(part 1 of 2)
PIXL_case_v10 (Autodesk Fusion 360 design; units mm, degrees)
part number: 0.96Oled_W_4_Buttons
base_feature "Base Feature"
work_plane "WorkPlane1" AlongDistance -6.5 ExtraOffset 0
sketch "Sketch1" plane through (0, 0, -6.5) normal (0, 0, 1) x axis (1, 0, 0)
  line L1 (24.2, -27.5) -> (-24.2, -27.5)
  line L2 (24.2, 15.7) -> (24.2, -27.5)
  line L3 (-24.2, 15.7) -> (24.2, 15.7)
  line L4 (-24.2, -27.5) -> (-24.2, 15.7)
extrude "Extrude1" new body sketch "Sketch1" along normal blind 11.8
fillet "Fillet1" radius 5
fillet "Fillet2" radius 1.4
work_plane "WorkPlane2" AlongDistance -6.5 ExtraOffset 0
sketch "Sketch2" plane through (0, 0, -6.5) normal (0, 0, 1) x axis (1, 0, 0)
  line L1 (22.2, -25.5) -> (-22.2, -25.5)
  line L2 (22.2, 13.7) -> (22.2, -25.5)
  line L3 (-22.2, 13.7) -> (22.2, 13.7)
  line L4 (-22.2, -25.5) -> (-22.2, 13.7)
extrude "Extrude2" cut sketch "Sketch2" along normal blind 9.3
fillet "Fillet3" radius 1.7
work_plane "WorkPlane3" AlongDistance 2.79 ExtraOffset 0
sketch "Sketch3" plane through (0, 0, 2.79) normal (0, 0, 1) x axis (1, 0, 0)
  line L1 (20.7, -11.3) -> (11, -11.3)
  line L2 (20.7, 11.7) -> (20.7, -11.3)
  line L3 (11, 11.7) -> (20.7, 11.7)
  line L4 (11, -11.3) -> (11, 11.7)
extrude "Extrude3" cut sketch "Sketch3" along normal blind 1.56
work_plane "WorkPlane4" AlongDistance 2.79 ExtraOffset 0
sketch "Sketch4" plane through (0, 0, 2.79) normal (0, 0, 1) x axis (1, 0, 0)
  line L1 (10, 9.6) -> (-10.8, 9.6)
  line L2 (10, 12.2) -> (10, 9.6)
  line L3 (-10.8, 12.2) -> (10, 12.2)
  line L4 (-10.8, 9.6) -> (-10.8, 12.2)
extrude "Extrude4" cut sketch "Sketch4" along normal blind 0.91
work_plane "WorkPlane5" AlongDistance 4.34 ExtraOffset 0
sketch "Sketch5" plane through (0, 0, 4.34) normal (0, 0, 1) x axis (1, 0, 0)
  line L1 (12.1, 5.6) -> (11.5, 5.6)
  line L2 (12.1, 11.8) -> (12.1, 5.6)
  line L3 (11.5, 11.8) -> (12.1, 11.8)
  line L4 (11.5, 5.6) -> (11.5, 11.8)
extrude "Extrude5" cut sketch "Sketch5" along normal blind 1.06
work_plane "WorkPlane6" AlongDistance 4.34 ExtraOffset 0
sketch "Sketch6" plane through (0, 0, 4.34) normal (0, 0, 1) x axis (1, 0, 0)
  line L1 (19.6, 11.2) -> (11.5, 11.2)
  line L2 (19.6, 11.8) -> (19.6, 11.2)
  line L3 (11.5, 11.8) -> (19.6, 11.8)
  line L4 (11.5, 11.2) -> (11.5, 11.8)
extrude "Extrude6" cut sketch "Sketch6" along normal blind 1.06
work_plane "WorkPlane7" AlongDistance 4.34 ExtraOffset 0
sketch "Sketch7" plane through (0, 0, 4.34) normal (0, 0, 1) x axis (1, 0, 0)
  line L1 (19.6, 5.6) -> (11.5, 5.6)
  line L2 (19.6, 6.2) -> (19.6, 5.6)
  line L3 (11.5, 6.2) -> (19.6, 6.2)
  line L4 (11.5, 5.6) -> (11.5, 6.2)
extrude "Extrude7" cut sketch "Sketch7" along normal blind 1.06
work_plane "WorkPlane8" AlongDistance 4.34 ExtraOffset 0
sketch "Sketch8" plane through (0, 0, 4.34) normal (0, 0, 1) x axis (1, 0, 0)
  line L1 (12.1, -0.07) -> (11.5, -0.07)
  line L2 (12.1, 6.13) -> (12.1, -0.07)
  line L3 (11.5, 6.13) -> (12.1, 6.13)
  line L4 (11.5, -0.07) -> (11.5, 6.13)
extrude "Extrude8" cut sketch "Sketch8" along normal blind 1.06
work_plane "WorkPlane9" AlongDistance 4.34 ExtraOffset 0
sketch "Sketch9" plane through (0, 0, 4.34) normal (0, 0, 1) x axis (1, 0, 0)
  line L1 (19.6, 5.53) -> (11.5, 5.53)
  line L2 (19.6, 6.13) -> (19.6, 5.53)
  line L3 (11.5, 6.13) -> (19.6, 6.13)
  line L4 (11.5, 5.53) -> (11.5, 6.13)
extrude "Extrude9" cut sketch "Sketch9" along normal blind 1.06
work_plane "WorkPlane10" AlongDistance 4.34 ExtraOffset 0
sketch "Sketch10" plane through (0, 0, 4.34) normal (0, 0, 1) x axis (1, 0, 0)
  line L1 (19.6, -0.07) -> (11.5, -0.07)
  line L2 (19.6, 0.53) -> (19.6, -0.07)
  line L3 (11.5, 0.53) -> (19.6, 0.53)
  line L4 (11.5, -0.07) -> (11.5, 0.53)
extrude "Extrude10" cut sketch "Sketch10" along normal blind 1.06
work_plane "WorkPlane11" AlongDistance 4.34 ExtraOffset 0
sketch "Sketch11" plane through (0, 0, 4.34) normal (0, 0, 1) x axis (1, 0, 0)
  line L1 (12.1, -5.73) -> (11.5, -5.73)
  line L2 (12.1, 0.47) -> (12.1, -5.73)
  line L3 (11.5, 0.47) -> (12.1, 0.47)
  line L4 (11.5, -5.73) -> (11.5, 0.47)
extrude "Extrude11" cut sketch "Sketch11" along normal blind 1.06
work_plane "WorkPlane12" AlongDistance 4.34 ExtraOffset 0
sketch "Sketch12" plane through (0, 0, 4.34) normal (0, 0, 1) x axis (1, 0, 0)
  line L1 (19.6, -0.13) -> (11.5, -0.13)
  line L2 (19.6, 0.47) -> (19.6, -0.13)
  line L3 (11.5, 0.47) -> (19.6, 0.47)
  line L4 (11.5, -0.13) -> (11.5, 0.47)
extrude "Extrude12" cut sketch "Sketch12" along normal blind 1.06
work_plane "WorkPlane13" AlongDistance 4.34 ExtraOffset 0
sketch "Sketch13" plane through (0, 0, 4.34) normal (0, 0, 1) x axis (1, 0, 0)
  line L1 (19.6, -5.73) -> (11.5, -5.73)
  line L2 (19.6, -5.13) -> (19.6, -5.73)
  line L3 (11.5, -5.13) -> (19.6, -5.13)
  line L4 (11.5, -5.73) -> (11.5, -5.13)
extrude "Extrude13" cut sketch "Sketch13" along normal blind 1.06
work_plane "WorkPlane14" AlongDistance 4.34 ExtraOffset 0
sketch "Sketch14" plane through (0, 0, 4.34) normal (0, 0, 1) x axis (1, 0, 0)
  line L1 (12.1, -11.4) -> (11.5, -11.4)
  line L2 (12.1, -5.2) -> (12.1, -11.4)
  line L3 (11.5, -5.2) -> (12.1, -5.2)
  line L4 (11.5, -11.4) -> (11.5, -5.2)
extrude "Extrude14" cut sketch "Sketch14" along normal blind 1.06
work_plane "WorkPlane15" AlongDistance 4.34 ExtraOffset 0
sketch "Sketch15" plane through (0, 0, 4.34) normal (0, 0, 1) x axis (1, 0, 0)
  line L1 (19.6, -5.8) -> (11.5, -5.8)
  line L2 (19.6, -5.2) -> (19.6, -5.8)
  line L3 (11.5, -5.2) -> (19.6, -5.2)
  line L4 (11.5, -5.8) -> (11.5, -5.2)
extrude "Extrude15" cut sketch "Sketch15" along normal blind 1.06
work_plane "WorkPlane16" AlongDistance 4.34 ExtraOffset 0
sketch "Sketch16" plane through (0, 0, 4.34) normal (0, 0, 1) x axis (1, 0, 0)
  line L1 (19.6, -11.4) -> (11.5, -11.4)
  line L2 (19.6, -10.8) -> (19.6, -11.4)
  line L3 (11.5, -10.8) -> (19.6, -10.8)
  line L4 (11.5, -11.4) -> (11.5, -10.8)
extrude "Extrude16" cut sketch "Sketch16" along normal blind 1.06
work_plane "WorkPlane17" AlongDistance 4.34 ExtraOffset 0
sketch "Sketch17" plane through (0, 0, 4.34) normal (0, 0, 1) x axis (1, 0, 0)
  line L1 (20.7, 6.2) -> (18.4, 6.2)
  line L2 (20.7, 11.2) -> (20.7, 6.2)
  line L3 (18.4, 11.2) -> (20.7, 11.2)
  line L4 (18.4, 6.2) -> (18.4, 11.2)
extrude "Extrude17" cut sketch "Sketch17" along normal blind 0.46
work_plane "WorkPlane18" AlongDistance 4.34 ExtraOffset 0
sketch "Sketch18" plane through (0, 0, 4.34) normal (0, 0, 1) x axis (1, 0, 0)
  line L1 (20.7, 0.53) -> (18.4, 0.53)
  line L2 (20.7, 5.53) -> (20.7, 0.53)
  line L3 (18.4, 5.53) -> (20.7, 5.53)
  line L4 (18.4, 0.53) -> (18.4, 5.53)
extrude "Extrude18" cut sketch "Sketch18" along normal blind 0.46
work_plane "WorkPlane19" AlongDistance 4.34 ExtraOffset 0
sketch "Sketch19" plane through (0, 0, 4.34) normal (0, 0, 1) x axis (1, 0, 0)
  line L1 (20.7, -5.13) -> (18.4, -5.13)
  line L2 (20.7, -0.13) -> (20.7, -5.13)
  line L3 (18.4, -0.13) -> (20.7, -0.13)
  line L4 (18.4, -5.13) -> (18.4, -0.13)
extrude "Extrude19" cut sketch "Sketch19" along normal blind 0.46
work_plane "WorkPlane20" AlongDistance 4.34 ExtraOffset 0
sketch "Sketch20" plane through (0, 0, 4.34) normal (0, 0, 1) x axis (1, 0, 0)
  line L1 (20.7, -10.8) -> (18.4, -10.8)
  line L2 (20.7, -5.8) -> (20.7, -10.8)
  line L3 (18.4, -5.8) -> (20.7, -5.8)
  line L4 (18.4, -10.8) -> (18.4, -5.8)
extrude "Extrude20" cut sketch "Sketch20" along normal blind 0.46
work_plane "WorkPlane21" AlongDistance 2.79 ExtraOffset 0
sketch "Sketch21" plane through (0, 0, 2.79) normal (0, 0, 1) x axis (1, 0, 0)
  line L1 (7, -6.6) -> (-16.3, -6.6)
  line L2 (7, 6.4) -> (7, -6.6)
  line L3 (-16.3, 6.4) -> (7, 6.4)
  line L4 (-16.3, -6.6) -> (-16.3, 6.4)
extrude "Extrude21" cut sketch "Sketch21" along normal blind 2.61
chamfer "Chamfer1" distance 1.2
work_plane "WorkPlane22" AlongDistance 1.6 ExtraOffset 0
sketch "Sketch22" plane through (0, 0, 1.6) normal (0, 0, 1) x axis (1, 0, 0)
  circle C1 centre (-20.5, -12) radius 1.5
extrude "Extrude22" add sketch "Sketch22" along normal blind 1.21
work_plane "WorkPlane23" AlongDistance 1.6 ExtraOffset 0
sketch "Sketch23" plane through (0, 0, 1.6) normal (0, 0, 1) x axis (1, 0, 0)
  circle C1 centre (-20.5, 12) radius 1.5
extrude "Extrude23" add sketch "Sketch23" along normal blind 1.21
work_plane "WorkPlane24" AlongDistance 1.6 ExtraOffset 0
sketch "Sketch24" plane through (0, 0, 1.6) normal (0, 0, 1) x axis (1, 0, 0)
  circle C1 centre (20.5, -12) radius 1.5
extrude "Extrude24" add sketch "Sketch24" along normal blind 1.21
work_plane "WorkPlane25" AlongDistance 1.6 ExtraOffset 0
sketch "Sketch25" plane through (0, 0, 1.6) normal (0, 0, 1) x axis (1, 0, 0)
  circle C1 centre (20.5, 12) radius 1.5
extrude "Extrude25" add sketch "Sketch25" along normal blind 1.21
work_plane "WorkPlane26" AlongDistance 5.3 ExtraOffset 0
sketch "Sketch26" plane through (0, 0, 5.3) normal (0, 0, 1) x axis (1, 0, 0)
  line L1 (-16.5, -17.8) -> (-19.8, -17.8)
  line L2 (-16.5, -16.7) -> (-16.5, -17.8)
  line L3 (-19.8, -16.7) -> (-16.5, -16.7)
  line L4 (-19.8, -17.8) -> (-19.8, -16.7)
  line L5 (-18.7, -18.9) -> (-19.8, -18.9)
  line L6 (-18.7, -17.8) -> (-18.7, -18.9)
  line L7 (-19.8, -17.8) -> (-18.7, -17.8)
  line L8 (-19.8, -18.9) -> (-19.8, -17.8)
  line L9 (-15.4, -18.9) -> (-16.5, -18.9)
  line L10 (-15.4, -17.8) -> (-15.4, -18.9)
  line L11 (-16.5, -17.8) -> (-15.4, -17.8)
  line L12 (-16.5, -18.9) -> (-16.5, -17.8)
  line L13 (-18.7, -20) -> (-19.8, -20)
  line L14 (-18.7, -18.9) -> (-18.7, -20)
  line L15 (-19.8, -18.9) -> (-18.7, -18.9)
  line L16 (-19.8, -20) -> (-19.8, -18.9)
  line L17 (-15.4, -20) -> (-16.5, -20)
  line L18 (-15.4, -18.9) -> (-15.4, -20)
  line L19 (-16.5, -18.9) -> (-15.4, -18.9)
  line L20 (-16.5, -20) -> (-16.5, -18.9)
  line L21 (-16.5, -21.1) -> (-19.8, -21.1)
  line L22 (-16.5, -20) -> (-16.5, -21.1)
  line L23 (-19.8, -20) -> (-16.5, -20)
  line L24 (-19.8, -21.1) -> (-19.8, -20)
  line L25 (-18.7, -22.2) -> (-19.8, -22.2)
  line L26 (-18.7, -21.1) -> (-18.7, -22.2)
  line L27 (-19.8, -21.1) -> (-18.7, -21.1)
  line L28 (-19.8, -22.2) -> (-19.8, -21.1)
  line L29 (-18.7, -23.3) -> (-19.8, -23.3)
  line L30 (-18.7, -22.2) -> (-18.7, -23.3)
  line L31 (-19.8, -22.2) -> (-18.7, -22.2)
  line L32 (-19.8, -23.3) -> (-19.8, -22.2)
  line L33 (-13.2, -17.8) -> (-14.3, -17.8)
  line L34 (-13.2, -16.7) -> (-13.2, -17.8)
  line L35 (-14.3, -16.7) -> (-13.2, -16.7)
  line L36 (-14.3, -17.8) -> (-14.3, -16.7)
  line L37 (-13.2, -20) -> (-14.3, -20)
  line L38 (-13.2, -18.9) -> (-13.2, -20)
  line L39 (-14.3, -18.9) -> (-13.2, -18.9)
  line L40 (-14.3, -20) -> (-14.3, -18.9)
  line L41 (-13.2, -21.1) -> (-14.3, -21.1)
  line L42 (-13.2, -20) -> (-13.2, -21.1)
  line L43 (-14.3, -20) -> (-13.2, -20)
  line L44 (-14.3, -21.1) -> (-14.3, -20)
  line L45 (-13.2, -22.2) -> (-14.3, -22.2)
  line L46 (-13.2, -21.1) -> (-13.2, -22.2)
  line L47 (-14.3, -21.1) -> (-13.2, -21.1)
  line L48 (-14.3, -22.2) -> (-14.3, -21.1)
  line L49 (-13.2, -23.3) -> (-14.3, -23.3)
  line L50 (-13.2, -22.2) -> (-13.2, -23.3)
  line L51 (-14.3, -22.2) -> (-13.2, -22.2)
  line L52 (-14.3, -23.3) -> (-14.3, -22.2)
  line L53 (-11, -17.8) -> (-12.1, -17.8)
  line L54 (-11, -16.7) -> (-11, -17.8)
  line L55 (-12.1, -16.7) -> (-11, -16.7)
  line L56 (-12.1, -17.8) -> (-12.1, -16.7)
  line L57 (-7.7, -17.8) -> (-8.8, -17.8)
  line L58 (-7.7, -16.7) -> (-7.7, -17.8)
  line L59 (-8.8, -16.7) -> (-7.7, -16.7)
  line L60 (-8.8, -17.8) -> (-8.8, -16.7)
  line L61 (-11, -18.9) -> (-12.1, -18.9)
  line L62 (-11, -17.8) -> (-11, -18.9)
  line L63 (-12.1, -17.8) -> (-11, -17.8)
  line L64 (-12.1, -18.9) -> (-12.1, -17.8)
  line L65 (-7.7, -18.9) -> (-8.8, -18.9)
  line L66 (-7.7, -17.8) -> (-7.7, -18.9)
  line L67 (-8.8, -17.8) -> (-7.7, -17.8)
  line L68 (-8.8, -18.9) -> (-8.8, -17.8)
  line L69 (-8.8, -20) -> (-11, -20)
  line L70 (-8.8, -18.9) -> (-8.8, -20)
  line L71 (-11, -18.9) -> (-8.8, -18.9)
  line L72 (-11, -20) -> (-11, -18.9)
  line L73 (-8.8, -21.1) -> (-11, -21.1)
  line L74 (-8.8, -20) -> (-8.8, -21.1)
  line L75 (-11, -20) -> (-8.8, -20)
  line L76 (-11, -21.1) -> (-11, -20)
  line L77 (-11, -22.2) -> (-12.1, -22.2)
  line L78 (-11, -21.1) -> (-11, -22.2)
  line L79 (-12.1, -21.1) -> (-11, -21.1)
  line L80 (-12.1, -22.2) -> (-12.1, -21.1)
  line L81 (-7.7, -22.2) -> (-8.8, -22.2)
  line L82 (-7.7, -21.1) -> (-7.7, -22.2)
  line L83 (-8.8, -21.1) -> (-7.7, -21.1)
  line L84 (-8.8, -22.2) -> (-8.8, -21.1)
  line L85 (-11, -23.3) -> (-12.1, -23.3)
  line L86 (-11, -22.2) -> (-11, -23.3)
  line L87 (-12.1, -22.2) -> (-11, -22.2)
  line L88 (-12.1, -23.3) -> (-12.1, -22.2)
  line L89 (-7.7, -23.3) -> (-8.8, -23.3)
  line L90 (-7.7, -22.2) -> (-7.7, -23.3)
  line L91 (-8.8, -22.2) -> (-7.7, -22.2)
  line L92 (-8.8, -23.3) -> (-8.8, -22.2)
  line L93 (-5.5, -17.8) -> (-6.6, -17.8)
  line L94 (-5.5, -16.7) -> (-5.5, -17.8)
  line L95 (-6.6, -16.7) -> (-5.5, -16.7)
  line L96 (-6.6, -17.8) -> (-6.6, -16.7)
  line L97 (-5.5, -18.9) -> (-6.6, -18.9)
  line L98 (-5.5, -17.8) -> (-5.5, -18.9)
  line L99 (-6.6, -17.8) -> (-5.5, -17.8)
  line L100 (-6.6, -18.9) -> (-6.6, -17.8)
  line L101 (-5.5, -20) -> (-6.6, -20)
  line L102 (-5.5, -18.9) -> (-5.5, -20)
  line L103 (-6.6, -18.9) -> (-5.5, -18.9)
  line L104 (-6.6, -20) -> (-6.6, -18.9)
  line L105 (-5.5, -21.1) -> (-6.6, -21.1)
  line L106 (-5.5, -20) -> (-5.5, -21.1)
  line L107 (-6.6, -20) -> (-5.5, -20)
  line L108 (-6.6, -21.1) -> (-6.6, -20)
  line L109 (-5.5, -22.2) -> (-6.6, -22.2)
  line L110 (-5.5, -21.1) -> (-5.5, -22.2)
  line L111 (-6.6, -21.1) -> (-5.5, -21.1)
  line L112 (-6.6, -22.2) -> (-6.6, -21.1)
  line L113 (-2.2, -23.3) -> (-6.6, -23.3)
  line L114 (-2.2, -22.2) -> (-2.2, -23.3)
  line L115 (-6.6, -22.2) -> (-2.2, -22.2)
  line L116 (-6.6, -23.3) -> (-6.6, -22.2)
extrude "Extrude26" cut sketch "Sketch26" against normal blind 0.4
work_plane "WorkPlane27" AlongDistance 5.3 ExtraOffset 0
sketch "Sketch27" plane through (0, 0, 5.3) normal (0, 0, 1) x axis (1, 0, 0)
  line L1 (3.25, -22.25) -> (2.5, -22.25)
  line L2 (3.25, -21.5) -> (3.25, -22.25)
  line L3 (2.5, -21.5) -> (3.25, -21.5)
  line L4 (2.5, -22.25) -> (2.5, -21.5)
  line L5 (4.5, -22.25) -> (3.75, -22.25)
  line L6 (4.5, -21.5) -> (4.5, -22.25)
  line L7 (3.75, -21.5) -> (4.5, -21.5)
  line L8 (3.75, -22.25) -> (3.75, -21.5)
  line L9 (5.75, -22.25) -> (5, -22.25)
  line L10 (5.75, -21.5) -> (5.75, -22.25)
  line L11 (5, -21.5) -> (5.75, -21.5)
  line L12 (5, -22.25) -> (5, -21.5)
  line L13 (7, -22.25) -> (6.25, -22.25)
  line L14 (7, -21.5) -> (7, -22.25)
  line L15 (6.25, -21.5) -> (7, -21.5)
  line L16 (6.25, -22.25) -> (6.25, -21.5)
  line L17 (8.25, -22.25) -> (7.5, -22.25)
  line L18 (8.25, -21.5) -> (8.25, -22.25)
  line L19 (7.5, -21.5) -> (8.25, -21.5)
  line L20 (7.5, -22.25) -> (7.5, -21.5)
  line L21 (9.5, -22.25) -> (8.75, -22.25)
  line L22 (9.5, -21.5) -> (9.5, -22.25)
  line L23 (8.75, -21.5) -> (9.5, -21.5)
  line L24 (8.75, -22.25) -> (8.75, -21.5)
  line L25 (10.75, -22.25) -> (10, -22.25)
  line L26 (10.75, -21.5) -> (10.75, -22.25)
  line L27 (10, -21.5) -> (10.75, -21.5)
  line L28 (10, -22.25) -> (10, -21.5)
  line L29 (13.25, -22.25) -> (12.5, -22.25)
  line L30 (13.25, -21.5) -> (13.25, -22.25)
  line L31 (12.5, -21.5) -> (13.25, -21.5)
  line L32 (12.5, -22.25) -> (12.5, -21.5)
  line L33 (15.75, -22.25) -> (15, -22.25)
  line L34 (15.75, -21.5) -> (15.75, -22.25)
  line L35 (15, -21.5) -> (15.75, -21.5)
  line L36 (15, -22.25) -> (15, -21.5)
  line L37 (3.25, -21) -> (2.5, -21)
  line L38 (3.25, -20.25) -> (3.25, -21)
  line L39 (2.5, -20.25) -> (3.25, -20.25)
  line L40 (2.5, -21) -> (2.5, -20.25)
  line L41 (4.5, -21) -> (3.75, -21)
  line L42 (4.5, -20.25) -> (4.5, -21)
  line L43 (3.75, -20.25) -> (4.5, -20.25)
  line L44 (3.75, -21) -> (3.75, -20.25)
  line L45 (7, -21) -> (6.25, -21)
  line L46 (7, -20.25) -> (7, -21)
  line L47 (6.25, -20.25) -> (7, -20.25)
  line L48 (6.25, -21) -> (6.25, -20.25)
  line L49 (9.5, -21) -> (8.75, -21)
  line L50 (9.5, -20.25) -> (9.5, -21)
  line L51 (8.75, -20.25) -> (9.5, -20.25)
  line L52 (8.75, -21) -> (8.75, -20.25)
  line L53 (12, -21) -> (11.25, -21)
  line L54 (12, -20.25) -> (12, -21)
  line L55 (11.25, -20.25) -> (12, -20.25)
  line L56 (11.25, -21) -> (11.25, -20.25)
  line L57 (3.25, -19.75) -> (2.5, -19.75)
  line L58 (3.25, -19) -> (3.25, -19.75)
  line L59 (2.5, -19) -> (3.25, -19)
  line L60 (2.5, -19.75) -> (2.5, -19)
  line L61 (4.5, -19.75) -> (3.75, -19.75)
  line L62 (4.5, -19) -> (4.5, -19.75)
  line L63 (3.75, -19) -> (4.5, -19)
  line L64 (3.75, -19.75) -> (3.75, -19)
  line L65 (5.75, -19.75) -> (5, -19.75)
  line L66 (5.75, -19) -> (5.75, -19.75)
  line L67 (5, -19) -> (5.75, -19)
  line L68 (5, -19.75) -> (5, -19)
  line L69 (7, -19.75) -> (6.25, -19.75)
  line L70 (7, -19) -> (7, -19.75)
  line L71 (6.25, -19) -> (7, -19)
  line L72 (6.25, -19.75) -> (6.25, -19)
  line L73 (8.25, -19.75) -> (7.5, -19.75)
  line L74 (8.25, -19) -> (8.25, -19.75)
  line L75 (7.5, -19) -> (8.25, -19)
  line L76 (7.5, -19.75) -> (7.5, -19)
  line L77 (10.75, -19.75) -> (10, -19.75)
  line L78 (10.75, -19) -> (10.75, -19.75)
  line L79 (10, -19) -> (10.75, -19)
  line L80 (10, -19.75) -> (10, -19)
  line L81 (13.25, -19.75) -> (12.5, -19.75)
  line L82 (13.25, -19) -> (13.25, -19.75)
  line L83 (12.5, -19) -> (13.25, -19)
  line L84 (12.5, -19.75) -> (12.5, -19)
  line L85 (15.75, -19.75) -> (15, -19.75)
  line L86 (15.75, -19) -> (15.75, -19.75)
  line L87 (15, -19) -> (15.75, -19)
  line L88 (15, -19.75) -> (15, -19)
  line L89 (3.25, -18.5) -> (2.5, -18.5)
  line L90 (3.25, -17.75) -> (3.25, -18.5)
  line L91 (2.5, -17.75) -> (3.25, -17.75)
  line L92 (2.5, -18.5) -> (2.5, -17.75)
  line L93 (4.5, -18.5) -> (3.75, -18.5)
  line L94 (4.5, -17.75) -> (4.5, -18.5)
  line L95 (3.75, -17.75) -> (4.5, -17.75)
  line L96 (3.75, -18.5) -> (3.75, -17.75)
  line L97 (7, -18.5) -> (6.25, -18.5)
  line L98 (7, -17.75) -> (7, -18.5)
  line L99 (6.25, -17.75) -> (7, -17.75)
  line L100 (6.25, -18.5) -> (6.25, -17.75)
  line L101 (9.5, -18.5) -> (8.75, -18.5)
  line L102 (9.5, -17.75) -> (9.5, -18.5)
  line L103 (8.75, -17.75) -> (9.5, -17.75)
  line L104 (8.75, -18.5) -> (8.75, -17.75)
  line L105 (12, -18.5) -> (11.25, -18.5)
  line L106 (12, -17.75) -> (12, -18.5)
  line L107 (11.25, -17.75) -> (12, -17.75)
  line L108 (11.25, -18.5) -> (11.25, -17.75)
extrude "Extrude27" cut sketch "Sketch27" against normal blind 0.35
work_plane "WorkPlane28" AlongDistance 5.3 ExtraOffset 0
sketch "Sketch28" plane through (0, 0, 5.3) normal (0, 0, 1) x axis (1, 0, 0)
  line L1 (17.125, 9.375) -> (16.675, 9.375)
  line L2 (17.125, 9.825) -> (17.125, 9.375)
  line L3 (16.675, 9.825) -> (17.125, 9.825)
  line L4 (16.675, 9.375) -> (16.675, 9.825)
  line L5 (17.575, 8.925) -> (16.225, 8.925)
  line L6 (17.575, 9.375) -> (17.575, 8.925)
  line L7 (16.225, 9.375) -> (17.575, 9.375)
  line L8 (16.225, 8.925) -> (16.225, 9.375)
  line L9 (16.675, 8.475) -> (15.775, 8.475)
  line L10 (16.675, 8.925) -> (16.675, 8.475)
  line L11 (15.775, 8.925) -> (16.675, 8.925)
  line L12 (15.775, 8.475) -> (15.775, 8.925)
  line L13 (18.025, 8.475) -> (17.125, 8.475)
  line L14 (18.025, 8.925) -> (18.025, 8.475)
  line L15 (17.125, 8.925) -> (18.025, 8.925)
  line L16 (17.125, 8.475) -> (17.125, 8.925)
  line L17 (16.225, 8.025) -> (15.325, 8.025)
  line L18 (16.225, 8.475) -> (16.225, 8.025)
  line L19 (15.325, 8.475) -> (16.225, 8.475)
  line L20 (15.325, 8.025) -> (15.325, 8.475)
  line L21 (18.475, 8.025) -> (17.575, 8.025)
  line L22 (18.475, 8.475) -> (18.475, 8.025)
  line L23 (17.575, 8.475) -> (18.475, 8.475)
  line L24 (17.575, 8.025) -> (17.575, 8.475)
  line L25 (15.775, 7.575) -> (15.325, 7.575)
  line L26 (15.775, 8.025) -> (15.775, 7.575)
  line L27 (15.325, 8.025) -> (15.775, 8.025)
  line L28 (15.325, 7.575) -> (15.325, 8.025)
  line L29 (18.475, 7.575) -> (18.025, 7.575)
  line L30 (18.475, 8.025) -> (18.475, 7.575)
  line L31 (18.025, 8.025) -> (18.475, 8.025)
  line L32 (18.025, 7.575) -> (18.025, 8.025)
  line L33 (15.775, 3.705) -> (15.325, 3.705)
  line L34 (15.775, 4.155) -> (15.775, 3.705)
  line L35 (15.325, 4.155) -> (15.775, 4.155)
  line L36 (15.325, 3.705) -> (15.325, 4.155)
  line L37 (18.475, 3.705) -> (18.025, 3.705)
  line L38 (18.475, 4.155) -> (18.475, 3.705)
  line L39 (18.025, 4.155) -> (18.475, 4.155)
  line L40 (18.025, 3.705) -> (18.025, 4.155)
  line L41 (16.225, 3.255) -> (15.325, 3.255)
  line L42 (16.225, 3.705) -> (16.225, 3.255)
  line L43 (15.325, 3.705) -> (16.225, 3.705)
  line L44 (15.325, 3.255) -> (15.325, 3.705)
  line L45 (18.475, 3.255) -> (17.575, 3.255)
  line L46 (18.475, 3.705) -> (18.475, 3.255)
  line L47 (17.575, 3.705) -> (18.475, 3.705)
  line L48 (17.575, 3.255) -> (17.575, 3.705)
  line L49 (16.675, 2.805) -> (15.775, 2.805)
  line L50 (16.675, 3.255) -> (16.675, 2.805)
  line L51 (15.775, 3.255) -> (16.675, 3.255)
  line L52 (15.775, 2.805) -> (15.775, 3.255)
  line L53 (18.025, 2.805) -> (17.125, 2.805)
  line L54 (18.025, 3.255) -> (18.025, 2.805)
  line L55 (17.125, 3.255) -> (18.025, 3.255)
  line L56 (17.125, 2.805) -> (17.125, 3.255)
  line L57 (17.575, 2.355) -> (16.225, 2.355)
  line L58 (17.575, 2.805) -> (17.575, 2.355)
  line L59 (16.225, 2.805) -> (17.575, 2.805)
  line L60 (16.225, 2.355) -> (16.225, 2.805)
  line L61 (17.125, 1.905) -> (16.675, 1.905)
  line L62 (17.125, 2.355) -> (17.125, 1.905)
  line L63 (16.675, 2.355) -> (17.125, 2.355)
  line L64 (16.675, 1.905) -> (16.675, 2.355)
  line L65 (18.475, -1.955) -> (15.325, -1.955)
  line L66 (18.475, -1.505) -> (18.475, -1.955)
  line L67 (15.325, -1.505) -> (18.475, -1.505)
  line L68 (15.325, -1.955) -> (15.325, -1.505)
  line L69 (18.475, -2.855) -> (15.325, -2.855)
  line L70 (18.475, -2.405) -> (18.475, -2.855)
  line L71 (15.325, -2.405) -> (18.475, -2.405)
  line L72 (15.325, -2.855) -> (15.325, -2.405)
  line L73 (18.475, -3.755) -> (15.325, -3.755)
  line L74 (18.475, -3.305) -> (18.475, -3.755)
  line L75 (15.325, -3.305) -> (18.475, -3.305)
  line L76 (15.325, -3.755) -> (15.325, -3.305)
  line L77 (16.675, -7.175) -> (16.225, -7.175)
  line L78 (16.675, -6.725) -> (16.675, -7.175)
  line L79 (16.225, -6.725) -> (16.675, -6.725)
  line L80 (16.225, -7.175) -> (16.225, -6.725)
  line L81 (16.675, -7.625) -> (15.775, -7.625)
  line L82 (16.675, -7.175) -> (16.675, -7.625)
  line L83 (15.775, -7.175) -> (16.675, -7.175)
  line L84 (15.775, -7.625) -> (15.775, -7.175)
  line L85 (18.025, -8.075) -> (15.325, -8.075)
  line L86 (18.025, -7.625) -> (18.025, -8.075)
  line L87 (15.325, -7.625) -> (18.025, -7.625)
  line L88 (15.325, -8.075) -> (15.325, -7.625)
  line L89 (16.675, -8.525) -> (15.775, -8.525)
  line L90 (16.675, -8.075) -> (16.675, -8.525)
  line L91 (15.775, -8.075) -> (16.675, -8.075)
  line L92 (15.775, -8.525) -> (15.775, -8.075)
  line L93 (18.475, -8.525) -> (18.025, -8.525)
  line L94 (18.475, -8.075) -> (18.475, -8.525)
  line L95 (18.025, -8.075) -> (18.475, -8.075)
  line L96 (18.025, -8.525) -> (18.025, -8.075)
  line L97 (16.675, -8.975) -> (16.225, -8.975)
  line L98 (16.675, -8.525) -> (16.675, -8.975)
  line L99 (16.225, -8.525) -> (16.675, -8.525)
  line L100 (16.225, -8.975) -> (16.225, -8.525)
  line L101 (18.475, -8.975) -> (18.025, -8.975)
  line L102 (18.475, -8.525) -> (18.475, -8.975)
  line L103 (18.025, -8.525) -> (18.475, -8.525)
  line L104 (18.025, -8.975) -> (18.025, -8.525)
  line L105 (18.475, -9.425) -> (18.025, -9.425)
  line L106 (18.475, -8.975) -> (18.475, -9.425)
  line L107 (18.025, -8.975) -> (18.475, -8.975)
  line L108 (18.025, -9.425) -> (18.025, -8.975)
  line L109 (18.025, -9.875) -> (15.775, -9.875)
  line L110 (18.025, -9.425) -> (18.025, -9.875)
  line L111 (15.775, -9.425) -> (18.025, -9.425)
  line L112 (15.775, -9.875) -> (15.775, -9.425)
extrude "Extrude28" cut sketch "Sketch28" against normal blind 0.3
work_plane "WorkPlane29" AlongDistance -4.9 ExtraOffset 0
sketch "Sketch29" plane through (0, 0, -4.9) normal (0, 0, 1) x axis (1, 0, 0)
  line L1 (24.7, -21) -> (21.7, -21)
  line L2 (24.7, -11) -> (24.7, -21)
  line L3 (21.7, -11) -> (24.7, -11)
  line L4 (21.7, -21) -> (21.7, -11)
extrude "Extrude29" cut sketch "Sketch29" along normal blind 4
work_plane "WorkPlane30" AlongDistance -5.9 ExtraOffset 0
sketch "Sketch30" plane through (0, 0, -5.9) normal (0, 0, 1) x axis (1, 0, 0)
  line L1 (24.7, -22.5) -> (23.2, -22.5)
  line L2 (24.7, -9.5) -> (24.7, -22.5)
  line L3 (23.2, -9.5) -> (24.7, -9.5)
  line L4 (23.2, -22.5) -> (23.2, -9.5)
extrude "Extrude30" cut sketch "Sketch30" along normal blind 6
work_plane "WorkPlane31" AlongDistance -6.6 ExtraOffset 0
sketch "Sketch31" plane through (0, 0, -6.6) normal (0, 0, 1) x axis (1, 0, 0)
  line L1 (-22.1, -21) -> (-24.3, -21)
  line L2 (-22.1, -20.5) -> (-22.1, -21)
  line L3 (-24.3, -20.5) -> (-22.1, -20.5)
  line L4 (-24.3, -21) -> (-24.3, -20.5)
extrude "Extrude31" cut sketch "Sketch31" along normal blind 4.1
work_plane "WorkPlane32" AlongDistance -3 ExtraOffset 0
sketch "Sketch32" plane through (0, 0, -3) normal (0, 0, 1) x axis (1, 0, 0)
  line L1 (-22.1, -21) -> (-24.3, -21)
  line L2 (-22.1, -15.5) -> (-22.1, -21)
  line L3 (-24.3, -15.5) -> (-22.1, -15.5)
  line L4 (-24.3, -21) -> (-24.3, -15.5)
extrude "Extrude32" cut sketch "Sketch32" along normal blind 0.5
work_plane "WorkPlane33" AlongDistance -6.6 ExtraOffset 0
sketch "Sketch33" plane through (0, 0, -6.6) normal (0, 0, 1) x axis (1, 0, 0)
  line L1 (-22.1, -20.5) -> (-24.3, -20.5)
  line L2 (-22.1, -15.5) -> (-22.1, -20.5)
  line L3 (-24.3, -15.5) -> (-22.1, -15.5)
  line L4 (-24.3, -20.5) -> (-24.3, -15.5)
extrude "Extrude33" cut sketch "Sketch33" along normal blind 0.3
work_plane "WorkPlane34" AlongDistance -6.35 ExtraOffset 0
sketch "Sketch34" plane through (0, 0, -6.35) normal (0, 0, 1) x axis (1, 0, 0)
  line L1 (-22.1, -20.5) -> (-23.2, -20.5)
  line L2 (-22.1, -15.6) -> (-22.1, -20.5)
  line L3 (-23.2, -15.6) -> (-22.1, -15.6)
  line L4 (-23.2, -20.5) -> (-23.2, -15.6)
extrude "Extrude34" cut sketch "Sketch34" along normal blind 3.35
work_plane "WorkPlane35" AlongDistance -5.5 ExtraOffset 0
sketch "Sketch35" plane through (0, 0, -5.5) normal (0, 0, 1) x axis (1, 0, 0)
  line L1 (-22.45, -18.9) -> (-23.25, -18.9)
  line L2 (-22.45, -17.1) -> (-22.45, -18.9)
  line L3 (-23.25, -17.1) -> (-22.45, -17.1)
  line L4 (-23.25, -18.9) -> (-23.25, -17.1)
extrude "Extrude35" add sketch "Sketch35" along normal blind 1.8
work_plane "WorkPlane36" AlongDistance -6.3 ExtraOffset 0
sketch "Sketch36" plane through (0, 0, -6.3) normal (0, 0, 1) x axis (1, 0, 0)
  line L1 (-14.9, -21.3) -> (-15.7, -21.3)
  line L2 (-14.9, -14.7) -> (-14.9, -21.3)
  line L3 (-15.7, -14.7) -> (-14.9, -14.7)
  line L4 (-15.7, -21.3) -> (-15.7, -14.7)
extrude "Extrude36" add sketch "Sketch36" along normal blind 9.11
work_plane "WorkPlane37" AlongDistance -6.3 ExtraOffset 0
sketch "Sketch37" plane through (0, 0, -6.3) normal (0, 0, 1) x axis (1, 0, 0)
  line L1 (-14.9, -21.5) -> (-22.21, -21.5)
  line L2 (-14.9, -21.1) -> (-14.9, -21.5)
  line L3 (-22.21, -21.1) -> (-14.9, -21.1)
  line L4 (-22.21, -21.5) -> (-22.21, -21.1)
extrude "Extrude37" add sketch "Sketch37" along normal blind 9.11
work_plane "WorkPlane38" AlongDistance -6.3 ExtraOffset 0
sketch "Sketch38" plane through (0, 0, -6.3) normal (0, 0, 1) x axis (1, 0, 0)
  line L1 (-14.9, -14.9) -> (-22.21, -14.9)
  line L2 (-14.9, -14.5) -> (-14.9, -14.9)
  line L3 (-22.21, -14.5) -> (-14.9, -14.5)
  line L4 (-22.21, -14.9) -> (-22.21, -14.5)
extrude "Extrude38" add sketch "Sketch38" along normal blind 9.11
work_plane "WorkPlane39" AlongDistance -3.2 ExtraOffset 0
sketch "Sketch39" plane through (0, 0, -3.2) normal (0, 0, 1) x axis (1, 0, 0)
  line L1 (-22.2, -13.4) -> (-22.81, -13.4)
  line L2 (-22.2, -7.6) -> (-22.2, -13.4)
  line L3 (-22.81, -7.6) -> (-22.2, -7.6)
  line L4 (-22.81, -13.4) -> (-22.81, -7.6)
extrude "Extrude39" cut sketch "Sketch39" along normal blind 2
work_plane "WorkPlane40" AlongDistance -3.2 ExtraOffset 0
sketch "Sketch40" plane through (0, 0, -3.2) normal (0, 0, 1) x axis (1, 0, 0)
  line L1 (22.81, -7.2) -> (22.2, -7.2)
  line L2 (22.81, -0.8) -> (22.81, -7.2)
  line L3 (22.2, -0.8) -> (22.81, -0.8)
  line L4 (22.2, -7.2) -> (22.2, -0.8)
extrude "Extrude40" cut sketch "Sketch40" along normal blind 2
work_plane "WorkPlane41" AlongDistance -6 ExtraOffset 0
sketch "Sketch41" plane through (0, 0, -6) normal (0, 0, 1) x axis (1, 0, 0)
  line L1 (19.4, 13.6) -> (10.6, 13.6)
  line L2 (19.4, 14.6) -> (19.4, 13.6)
  line L3 (10.6, 14.6) -> (19.4, 14.6)
  line L4 (10.6, 13.6) -> (10.6, 14.6)
extrude "Extrude41" cut sketch "Sketch41" along normal blind 1.2
work_plane "WorkPlane42" AlongDistance -6.5 ExtraOffset 0
sketch "Sketch42" plane through (0, 0, -6.5) normal (0, 0, 1) x axis (1, 0, 0)
  line L1 (-10.2, -32.1) -> (-12.6, -32.1)
  line L2 (-10.2, -26.5) -> (-10.2, -32.1)
  line L3 (-12.6, -26.5) -> (-10.2, -26.5)
  line L4 (-12.6, -32.1) -> (-12.6, -26.5)
extrude "Extrude42" add sketch "Sketch42" along normal blind 3
work_plane "WorkPlane43" AlongDistance -7.7 ExtraOffset 0
sketch "Sketch43" plane through (0, 0, -7.7) normal (0, 0, 1) x axis (1, 0, 0)
  line L1 (-10.2, -32.1) -> (-12.6, -32.1)
  line L2 (-10.2, -27.7) -> (-10.2, -32.1)
  line L3 (-12.6, -27.7) -> (-10.2, -27.7)
  line L4 (-12.6, -32.1) -> (-12.6, -27.7)
extrude "Extrude43" add sketch "Sketch43" along normal blind 1.21
work_plane "WorkPlane44" AlongDistance -6.5 ExtraOffset 0
sketch "Sketch44" plane through (0, 0, -6.5) normal (0, 0, 1) x axis (1, 0, 0)
  line L1 (-10.2, 14.7) -> (-12.6, 14.7)
  line L2 (-10.2, 20.3) -> (-10.2, 14.7)
  line L3 (-12.6, 20.3) -> (-10.2, 20.3)
  line L4 (-12.6, 14.7) -> (-12.6, 20.3)
extrude "Extrude44" add sketch "Sketch44" along normal blind 3
work_plane "WorkPlane45" AlongDistance -7.7 ExtraOffset 0
sketch "Sketch45" plane through (0, 0, -7.7) normal (0, 0, 1) x axis (1, 0, 0)
  line L1 (-10.2, 15.9) -> (-12.6, 15.9)
  line L2 (-10.2, 20.3) -> (-10.2, 15.9)
  line L3 (-12.6, 20.3) -> (-10.2, 20.3)
  line L4 (-12.6, 15.9) -> (-12.6, 20.3)
extrude "Extrude45" add sketch "Sketch45" along normal blind 1.21
work_plane "WorkPlane46" AlongDistance -6.5 ExtraOffset 0
sketch "Sketch46" plane through (0, 0, -6.5) normal (0, 0, 1) x axis (1, 0, 0)
  line L1 (12.6, -32.1) -> (10.2, -32.1)
  line L2 (12.6, -26.5) -> (12.6, -32.1)
  line L3 (10.2, -26.5) -> (12.6, -26.5)
  line L4 (10.2, -32.1) -> (10.2, -26.5)
extrude "Extrude46" add sketch "Sketch46" along normal blind 3
work_plane "WorkPlane47" AlongDistance -7.7 ExtraOffset 0
sketch "Sketch47" plane through (0, 0, -7.7) normal (0, 0, 1) x axis (1, 0, 0)
  line L1 (12.6, -32.1) -> (10.2, -32.1)
  line L2 (12.6, -27.7) -> (12.6, -32.1)
  line L3 (10.2, -27.7) -> (12.6, -27.7)
  line L4 (10.2, -32.1) -> (10.2, -27.7)
extrude "Extrude47" add sketch "Sketch47" along normal blind 1.21
work_plane "WorkPlane48" AlongDistance -6.5 ExtraOffset 0
sketch "Sketch48" plane through (0, 0, -6.5) normal (0, 0, 1) x axis (1, 0, 0)
  line L1 (12.6, 14.7) -> (10.2, 14.7)
  line L2 (12.6, 20.3) -> (12.6, 14.7)
  line L3 (10.2, 20.3) -> (12.6, 20.3)
  line L4 (10.2, 14.7) -> (10.2, 20.3)
extrude "Extrude48" add sketch "Sketch48" along normal blind 3
work_plane "WorkPlane49" AlongDistance -7.7 ExtraOffset 0
sketch "Sketch49" plane through (0, 0, -7.7) normal (0, 0, 1) x axis (1, 0, 0)
  line L1 (12.6, 15.9) -> (10.2, 15.9)
  line L2 (12.6, 20.3) -> (12.6, 15.9)
  line L3 (10.2, 20.3) -> (12.6, 20.3)
  line L4 (10.2, 15.9) -> (10.2, 20.3)
extrude "Extrude49" add sketch "Sketch49" along normal blind 1.21
fillet "Fillet4" radius 1.2
sketch "Sketch50" plane through (0, 0, 0) normal (1, 0, 0) x axis (0, 0, -1)
  circle C1 centre (6.2, -30.3) radius 0.55
extrude "Extrude50" cut sketch "Sketch50" distance 13.6
sketch "Sketch51" plane through (0, 0, 0) normal (1, 0, 0) x axis (0, 0, -1)
  circle C1 centre (6.2, 18.5) radius 0.55
extrude "Extrude51" cut sketch "Sketch51" distance 13.6
work_plane "WorkPlane1" AlongDistance -7.7 ExtraOffset 0
sketch "Sketch1" plane through (0, 0, -7.7) normal (0, 0, 1) x axis (1, 0, 0)
  line L1 (24.2, -27.5) -> (-24.2, -27.5)
  line L2 (24.2, 15.7) -> (24.2, -27.5)
  line L3 (-24.2, 15.7) -> (24.2, 15.7)
  line L4 (-24.2, -27.5) -> (-24.2, 15.7)
extrude "Extrude1" new body sketch "Sketch1" along normal blind 1.2
fillet "Fillet1" radius 5
fillet "Fillet2" radius 0.6
work_plane "WorkPlane2" AlongDistance -6.51 ExtraOffset 0
sketch "Sketch2" plane through (0, 0, -6.51) normal (0, 0, 1) x axis (1, 0, 0)
  line L1 (21.95, -0.5) -> (20.95, -0.5)
  line L2 (21.95, 4) -> (21.95, -0.5)
  line L3 (20.95, 4) -> (21.95, 4)
  line L4 (20.95, -0.5) -> (20.95, 4)
extrude "Extrude2" add sketch "Sketch2" along normal blind 1.01
work_plane "WorkPlane3" AlongDistance -6.51 ExtraOffset 0
sketch "Sketch3" plane through (0, 0, -6.51) normal (0, 0, 1) x axis (1, 0, 0)
  line L1 (19, 12.6) -> (11, 12.6)
  line L2 (19, 13.55) -> (19, 12.6)
  line L3 (11, 13.55) -> (19, 13.55)
  line L4 (11, 12.6) -> (11, 13.55)
extrude "Extrude3" add sketch "Sketch3" along normal blind 1.61
work_plane "WorkPlane4" AlongDistance -5.8 ExtraOffset 0
sketch "Sketch4" plane through (0, 0, -5.8) normal (0, 0, 1) x axis (1, 0, 0)
  line L1 (19, 13.5) -> (11, 13.5)
  line L2 (19, 14.35) -> (19, 13.5)
  line L3 (11, 14.35) -> (19, 14.35)
  line L4 (11, 13.5) -> (11, 14.35)
extrude "Extrude4" add sketch "Sketch4" along normal blind 0.75
work_plane "WorkPlane5" AlongDistance -6.51 ExtraOffset 0
sketch "Sketch5" plane through (0, 0, -6.51) normal (0, 0, 1) x axis (1, 0, 0)
  line L1 (-21.25, -13) -> (-22.15, -13)
  line L2 (-21.25, -8) -> (-21.25, -13)
  line L3 (-22.15, -8) -> (-21.25, -8)
  line L4 (-22.15, -13) -> (-22.15, -8)
extrude "Extrude5" add sketch "Sketch5" along normal blind 5.41
work_plane "WorkPlane6" AlongDistance -3.1 ExtraOffset 0
sketch "Sketch6" plane through (0, 0, -3.1) normal (0, 0, 1) x axis (1, 0, 0)
  line L1 (-22.14, -12.7) -> (-22.4, -12.7)
  line L2 (-22.14, -8.3) -> (-22.14, -12.7)
  line L3 (-22.4, -8.3) -> (-22.14, -8.3)
  line L4 (-22.4, -12.7) -> (-22.4, -8.3)
extrude "Extrude6" add sketch "Sketch6" along normal blind 0.2
work_plane "WorkPlane7" AlongDistance -2.9 ExtraOffset 0
sketch "Sketch7" plane through (0, 0, -2.9) normal (0, 0, 1) x axis (1, 0, 0)
  line L1 (-22.14, -12.7) -> (-22.65, -12.7)
  line L2 (-22.14, -8.3) -> (-22.14, -12.7)
  line L3 (-22.65, -8.3) -> (-22.14, -8.3)
  line L4 (-22.65, -12.7) -> (-22.65, -8.3)
extrude "Extrude7" add sketch "Sketch7" along normal blind 0.5
work_plane "WorkPlane8" AlongDistance -2.4 ExtraOffset 0
sketch "Sketch8" plane through (0, 0, -2.4) normal (0, 0, 1) x axis (1, 0, 0)
  line L1 (-22.14, -12.7) -> (-22.48, -12.7)
  line L2 (-22.14, -8.3) -> (-22.14, -12.7)
  line L3 (-22.48, -8.3) -> (-22.14, -8.3)
  line L4 (-22.48, -12.7) -> (-22.48, -8.3)
extrude "Extrude8" add sketch "Sketch8" along normal blind 0.5
work_plane "WorkPlane9" AlongDistance -1.9 ExtraOffset 0
sketch "Sketch9" plane through (0, 0, -1.9) normal (0, 0, 1) x axis (1, 0, 0)
  line L1 (-22.14, -12.7) -> (-22.32, -12.7)
  line L2 (-22.14, -8.3) -> (-22.14, -12.7)
  line L3 (-22.32, -8.3) -> (-22.14, -8.3)
  line L4 (-22.32, -12.7) -> (-22.32, -8.3)
extrude "Extrude9" add sketch "Sketch9" along normal blind 0.5
work_plane "WorkPlane10" AlongDistance -6.51 ExtraOffset 0
sketch "Sketch10" plane through (0, 0, -6.51) normal (0, 0, 1) x axis (1, 0, 0)
  line L1 (22.15, -6.8) -> (21.25, -6.8)
  line L2 (22.15, -1.2) -> (22.15, -6.8)
  line L3 (21.25, -1.2) -> (22.15, -1.2)
  line L4 (21.25, -6.8) -> (21.25, -1.2)
extrude "Extrude10" add sketch "Sketch10" along normal blind 5.41
work_plane "WorkPlane11" AlongDistance -3.1 ExtraOffset 0
sketch "Sketch11" plane through (0, 0, -3.1) normal (0, 0, 1) x axis (1, 0, 0)
  line L1 (22.4, -6.5) -> (22.14, -6.5)
  line L2 (22.4, -1.5) -> (22.4, -6.5)
  line L3 (22.14, -1.5) -> (22.4, -1.5)
  line L4 (22.14, -6.5) -> (22.14, -1.5)
extrude "Extrude11" add sketch "Sketch11" along normal blind 0.2
work_plane "WorkPlane12" AlongDistance -2.9 ExtraOffset 0
sketch "Sketch12" plane through (0, 0, -2.9) normal (0, 0, 1) x axis (1, 0, 0)
  line L1 (22.65, -6.5) -> (22.14, -6.5)
  line L2 (22.65, -1.5) -> (22.65, -6.5)
  line L3 (22.14, -1.5) -> (22.65, -1.5)
  line L4 (22.14, -6.5) -> (22.14, -1.5)
extrude "Extrude12" add sketch "Sketch12" along normal blind 0.5
work_plane "WorkPlane13" AlongDistance -2.4 ExtraOffset 0
sketch "Sketch13" plane through (0, 0, -2.4) normal (0, 0, 1) x axis (1, 0, 0)
  line L1 (22.48, -6.5) -> (22.14, -6.5)
  line L2 (22.48, -1.5) -> (22.48, -6.5)
  line L3 (22.14, -1.5) -> (22.48, -1.5)
  line L4 (22.14, -6.5) -> (22.14, -1.5)
extrude "Extrude13" add sketch "Sketch13" along normal blind 0.5
work_plane "WorkPlane14" AlongDistance -1.9 ExtraOffset 0
sketch "Sketch14" plane through (0, 0, -1.9) normal (0, 0, 1) x axis (1, 0, 0)
  line L1 (22.32, -6.5) -> (22.14, -6.5)
  line L2 (22.32, -1.5) -> (22.32, -6.5)
  line L3 (22.14, -1.5) -> (22.32, -1.5)
  line L4 (22.14, -6.5) -> (22.14, -1.5)
extrude "Extrude14" add sketch "Sketch14" along normal blind 0.5
work_plane "WorkPlane15" AlongDistance -6.51 ExtraOffset 0
sketch "Sketch15" plane through (0, 0, -6.51) normal (0, 0, 1) x axis (1, 0, 0)
  circle C1 centre (20.6, 11.6) radius 0.8
extrude "Extrude15" add sketch "Sketch15" along normal blind 6.46
work_plane "WorkPlane16" AlongDistance -6.51 ExtraOffset 0
sketch "Sketch16" plane through (0, 0, -6.51) normal (0, 0, 1) x axis (1, 0, 0)
  circle C1 centre (-19.6, -10.5) radius 0.8
extrude "Extrude16" add sketch "Sketch16" along normal blind 6.46
work_plane "WorkPlane17" AlongDistance -6.51 ExtraOffset 0
sketch "Sketch17" plane through (0, 0, -6.51) normal (0, 0, 1) x axis (1, 0, 0)
  circle C1 centre (9.45, 3) radius 0.8
extrude "Extrude17" add sketch "Sketch17" along normal blind 6.46
work_plane "WorkPlane18" AlongDistance -7.8 ExtraOffset 0
sketch "Sketch18" plane through (0, 0, -7.8) normal (0, 0, 1) x axis (1, 0, 0)
  line L1 (4, -27.6) -> (-4, -27.6)
  line L2 (4, -26.5) -> (4, -27.6)
  line L3 (-4, -26.5) -> (4, -26.5)
  line L4 (-4, -27.6) -> (-4, -26.5)
extrude "Extrude18" cut sketch "Sketch18" along normal blind 0.65
work_plane "WorkPlane19" AlongDistance -6.8 ExtraOffset 0
sketch "Sketch19" plane through (0, 0, -6.8) normal (0, 0, 1) x axis (1, 0, 0)
  circle C1 centre (11, -15.3) radius 10.3
extrude "Extrude19" cut sketch "Sketch19" along normal blind 0.31
work_plane "WorkPlane20" AlongDistance -7.7 ExtraOffset 0
sketch "Sketch20" plane through (0, 0, -7.7) normal (0, 0, 1) x axis (1, 0, 0)
  line L1 (-11.95, -9.65) -> (-15.05, -9.65)
  line L2 (-9.75, -4.35) -> (-9.75, -7.45)
  line L3 (-15.05, -2.15) -> (-11.95, -2.15)
  line L4 (-17.25, -7.45) -> (-17.25, -4.35)
  line L5 (-11.95, -9.05) -> (-15.05, -9.05)
  line L6 (-10.35, -4.35) -> (-10.35, -7.45)
  line L7 (-15.05, -2.75) -> (-11.95, -2.75)
  line L8 (-16.65, -7.45) -> (-16.65, -4.35)
  arc A1 centre (-11.95, -7.45) radius 2.2 clockwise from (-9.75, -7.45) to (-11.95, -9.65)
  arc A2 centre (-11.95, -4.35) radius 2.2 clockwise from (-11.95, -2.15) to (-9.75, -4.35)
  arc A3 centre (-15.05, -4.35) radius 2.2 clockwise from (-17.25, -4.35) to (-15.05, -2.15)
  arc A4 centre (-15.05, -7.45) radius 2.2 clockwise from (-15.05, -9.65) to (-17.25, -7.45)
  arc A5 centre (-11.95, -7.45) radius 1.6 clockwise from (-10.35, -7.45) to (-11.95, -9.05)
  arc A6 centre (-11.95, -4.35) radius 1.6 clockwise from (-11.95, -2.75) to (-10.35, -4.35)
  arc A7 centre (-15.05, -4.35) radius 1.6 clockwise from (-16.65, -4.35) to (-15.05, -2.75)
  arc A8 centre (-15.05, -7.45) radius 1.6 clockwise from (-15.05, -9.05) to (-16.65, -7.45)
extrude "Extrude20" cut sketch "Sketch20" along normal blind 0.3
work_plane "WorkPlane21" AlongDistance -7.7 ExtraOffset 0
sketch "Sketch21" plane through (0, 0, -7.7) normal (0, 0, 1) x axis (1, 0, 0)
  line L1 (-2.95, -9.65) -> (-6.05, -9.65)
  line L2 (-0.75, -4.35) -> (-0.75, -7.45)
  line L3 (-6.05, -2.15) -> (-2.95, -2.15)
  line L4 (-8.25, -7.45) -> (-8.25, -4.35)
  line L5 (-2.95, -9.05) -> (-6.05, -9.05)
  line L6 (-1.35, -4.35) -> (-1.35, -7.45)
  line L7 (-6.05, -2.75) -> (-2.95, -2.75)
  line L8 (-7.65, -7.45) -> (-7.65, -4.35)
  arc A1 centre (-2.95, -7.45) radius 2.2 clockwise from (-0.75, -7.45) to (-2.95, -9.65)
  arc A2 centre (-2.95, -4.35) radius 2.2 clockwise from (-2.95, -2.15) to (-0.75, -4.35)
  arc A3 centre (-6.05, -4.35) radius 2.2 clockwise from (-8.25, -4.35) to (-6.05, -2.15)
  arc A4 centre (-6.05, -7.45) radius 2.2 clockwise from (-6.05, -9.65) to (-8.25, -7.45)
  arc A5 centre (-2.95, -7.45) radius 1.6 clockwise from (-1.35, -7.45) to (-2.95, -9.05)
  arc A6 centre (-2.95, -4.35) radius 1.6 clockwise from (-2.95, -2.75) to (-1.35, -4.35)
  arc A7 centre (-6.05, -4.35) radius 1.6 clockwise from (-7.65, -4.35) to (-6.05, -2.75)
  arc A8 centre (-6.05, -7.45) radius 1.6 clockwise from (-6.05, -9.05) to (-7.65, -7.45)
extrude "Extrude21" cut sketch "Sketch21" along normal blind 0.3
work_plane "WorkPlane22" AlongDistance -7.7 ExtraOffset 0
sketch "Sketch22" plane through (0, 0, -7.7) normal (0, 0, 1) x axis (1, 0, 0)
  line L1 (-5.7, -7.9) -> (-6.5, -7.9)
  line L2 (-5.7, -7.1) -> (-5.7, -7.9)
  line L3 (-6.5, -7.1) -> (-5.7, -7.1)
  line L4 (-6.5, -7.9) -> (-6.5, -7.1)
  line L5 (-4.1, -7.9) -> (-4.9, -7.9)
  line L6 (-4.1, -7.1) -> (-4.1, -7.9)
  line L7 (-4.9, -7.1) -> (-4.1, -7.1)
  line L8 (-4.9, -7.9) -> (-4.9, -7.1)
  line L9 (-2.5, -7.9) -> (-3.3, -7.9)
  line L10 (-2.5, -7.1) -> (-2.5, -7.9)
  line L11 (-3.3, -7.1) -> (-2.5, -7.1)
  line L12 (-3.3, -7.9) -> (-3.3, -7.1)
  line L13 (-5.7, -6.3) -> (-6.5, -6.3)
  line L14 (-5.7, -5.5) -> (-5.7, -6.3)
  line L15 (-6.5, -5.5) -> (-5.7, -5.5)
  line L16 (-6.5, -6.3) -> (-6.5, -5.5)
  line L17 (-4.1, -6.3) -> (-4.9, -6.3)
  line L18 (-4.1, -5.5) -> (-4.1, -6.3)
  line L19 (-4.9, -5.5) -> (-4.1, -5.5)
  line L20 (-4.9, -6.3) -> (-4.9, -5.5)
  line L21 (-2.5, -6.3) -> (-3.3, -6.3)
  line L22 (-2.5, -5.5) -> (-2.5, -6.3)
  line L23 (-3.3, -5.5) -> (-2.5, -5.5)
  line L24 (-3.3, -6.3) -> (-3.3, -5.5)
  line L25 (-5.7, -4.7) -> (-6.5, -4.7)
  line L26 (-5.7, -3.9) -> (-5.7, -4.7)
  line L27 (-6.5, -3.9) -> (-5.7, -3.9)
  line L28 (-6.5, -4.7) -> (-6.5, -3.9)
  line L29 (-4.1, -4.7) -> (-4.9, -4.7)
  line L30 (-4.1, -3.9) -> (-4.1, -4.7)
  line L31 (-4.9, -3.9) -> (-4.1, -3.9)
  line L32 (-4.9, -4.7) -> (-4.9, -3.9)
  line L33 (-2.5, -4.7) -> (-3.3, -4.7)
  line L34 (-2.5, -3.9) -> (-2.5, -4.7)
  line L35 (-3.3, -3.9) -> (-2.5, -3.9)
  line L36 (-3.3, -4.7) -> (-3.3, -3.9)
extrude "Extrude22" cut sketch "Sketch22" along normal blind 0.3
work_plane "WorkPlane23" AlongDistance -7.7 ExtraOffset 0
sketch "Sketch23" plane through (0, 0, -7.7) normal (0, 0, 1) x axis (1, 0, 0)
  line L1 (6.05, -9.65) -> (2.95, -9.65)
  line L2 (8.25, -4.35) -> (8.25, -7.45)
  line L3 (2.95, -2.15) -> (6.05, -2.15)
  line L4 (0.75, -7.45) -> (0.75, -4.35)
  line L5 (6.05, -9.05) -> (2.95, -9.05)
  line L6 (7.65, -4.35) -> (7.65, -7.45)
  line L7 (2.95, -2.75) -> (6.05, -2.75)
  line L8 (1.35, -7.45) -> (1.35, -4.35)
  arc A1 centre (6.05, -7.45) radius 2.2 clockwise from (8.25, -7.45) to (6.05, -9.65)
  arc A2 centre (6.05, -4.35) radius 2.2 clockwise from (6.05, -2.15) to (8.25, -4.35)
  arc A3 centre (2.95, -4.35) radius 2.2 clockwise from (0.75, -4.35) to (2.95, -2.15)
  arc A4 centre (2.95, -7.45) radius 2.2 clockwise from (2.95, -9.65) to (0.75, -7.45)
  arc A5 centre (6.05, -7.45) radius 1.6 clockwise from (7.65, -7.45) to (6.05, -9.05)
  arc A6 centre (6.05, -4.35) radius 1.6 clockwise from (6.05, -2.75) to (7.65, -4.35)
  arc A7 centre (2.95, -4.35) radius 1.6 clockwise from (1.35, -4.35) to (2.95, -2.75)
  arc A8 centre (2.95, -7.45) radius 1.6 clockwise from (2.95, -9.05) to (1.35, -7.45)
extrude "Extrude23" cut sketch "Sketch23" along normal blind 0.3
work_plane "WorkPlane24" AlongDistance -7.7 ExtraOffset 0
sketch "Sketch24" plane through (0, 0, -7.7) normal (0, 0, 1) x axis (1, 0, 0)
  line L1 (4.375, -8.325) -> (3.775, -8.325)
  line L2 (4.375, -7.725) -> (4.375, -8.325)
  line L3 (3.775, -7.725) -> (4.375, -7.725)
  line L4 (3.775, -8.325) -> (3.775, -7.725)
  line L5 (6.075, -8.325) -> (5.475, -8.325)
  line L6 (6.075, -7.725) -> (6.075, -8.325)
  line L7 (5.475, -7.725) -> (6.075, -7.725)
  line L8 (5.475, -8.325) -> (5.475, -7.725)
  line L9 (3.525, -7.475) -> (2.925, -7.475)
  line L10 (3.525, -6.875) -> (3.525, -7.475)
  line L11 (2.925, -6.875) -> (3.525, -6.875)
  line L12 (2.925, -7.475) -> (2.925, -6.875)
  line L13 (5.225, -7.475) -> (4.625, -7.475)
  line L14 (5.225, -6.875) -> (5.225, -7.475)
  line L15 (4.625, -6.875) -> (5.225, -6.875)
  line L16 (4.625, -7.475) -> (4.625, -6.875)
  line L17 (6.925, -7.475) -> (6.325, -7.475)
  line L18 (6.925, -6.875) -> (6.925, -7.475)
  line L19 (6.325, -6.875) -> (6.925, -6.875)
  line L20 (6.325, -7.475) -> (6.325, -6.875)
  line L21 (2.675, -6.625) -> (2.075, -6.625)
  line L22 (2.675, -6.025) -> (2.675, -6.625)
  line L23 (2.075, -6.025) -> (2.675, -6.025)
  line L24 (2.075, -6.625) -> (2.075, -6.025)
  line L25 (4.375, -6.625) -> (3.775, -6.625)
  line L26 (4.375, -6.025) -> (4.375, -6.625)
  line L27 (3.775, -6.025) -> (4.375, -6.025)
  line L28 (3.775, -6.625) -> (3.775, -6.025)
  line L29 (6.075, -6.625) -> (5.475, -6.625)
  line L30 (6.075, -6.025) -> (6.075, -6.625)
  line L31 (5.475, -6.025) -> (6.075, -6.025)
  line L32 (5.475, -6.625) -> (5.475, -6.025)
  line L33 (3.525, -5.775) -> (2.925, -5.775)
  line L34 (3.525, -5.175) -> (3.525, -5.775)
  line L35 (2.925, -5.175) -> (3.525, -5.175)
  line L36 (2.925, -5.775) -> (2.925, -5.175)
  line L37 (5.225, -5.775) -> (4.625, -5.775)
  line L38 (5.225, -5.175) -> (5.225, -5.775)
  line L39 (4.625, -5.175) -> (5.225, -5.175)
  line L40 (4.625, -5.775) -> (4.625, -5.175)
  line L41 (6.925, -5.775) -> (6.325, -5.775)
  line L42 (6.925, -5.175) -> (6.925, -5.775)
  line L43 (6.325, -5.175) -> (6.925, -5.175)
  line L44 (6.325, -5.775) -> (6.325, -5.175)
  line L45 (2.675, -4.925) -> (2.075, -4.925)
  line L46 (2.675, -4.325) -> (2.675, -4.925)
  line L47 (2.075, -4.325) -> (2.675, -4.325)
  line L48 (2.075, -4.925) -> (2.075, -4.325)
  line L49 (4.375, -4.925) -> (3.775, -4.925)
  line L50 (4.375, -4.325) -> (4.375, -4.925)
  line L51 (3.775, -4.325) -> (4.375, -4.325)
  line L52 (3.775, -4.925) -> (3.775, -4.325)
  line L53 (6.075, -4.925) -> (5.475, -4.925)
  line L54 (6.075, -4.325) -> (6.075, -4.925)
  line L55 (5.475, -4.325) -> (6.075, -4.325)
  line L56 (5.475, -4.925) -> (5.475, -4.325)
  line L57 (3.525, -4.075) -> (2.925, -4.075)
  line L58 (3.525, -3.475) -> (3.525, -4.075)
  line L59 (2.925, -3.475) -> (3.525, -3.475)
  line L60 (2.925, -4.075) -> (2.925, -3.475)
  line L61 (5.225, -4.075) -> (4.625, -4.075)
  line L62 (5.225, -3.475) -> (5.225, -4.075)
  line L63 (4.625, -3.475) -> (5.225, -3.475)
  line L64 (4.625, -4.075) -> (4.625, -3.475)
extrude "Extrude24" cut sketch "Sketch24" along normal blind 0.3
work_plane "WorkPlane25" AlongDistance -7.7 ExtraOffset 0
sketch "Sketch25" plane through (0, 0, -7.7) normal (0, 0, 1) x axis (1, 0, 0)
  line L1 (15.05, -9.65) -> (11.95, -9.65)
  line L2 (17.25, -4.35) -> (17.25, -7.45)
  line L3 (11.95, -2.15) -> (15.05, -2.15)
  line L4 (9.75, -7.45) -> (9.75, -4.35)
  arc A1 centre (15.05, -7.45) radius 2.2 clockwise from (17.25, -7.45) to (15.05, -9.65)
  arc A2 centre (15.05, -4.35) radius 2.2 clockwise from (15.05, -2.15) to (17.25, -4.35)
  arc A3 centre (11.95, -4.35) radius 2.2 clockwise from (9.75, -4.35) to (11.95, -2.15)
  arc A4 centre (11.95, -7.45) radius 2.2 clockwise from (11.95, -9.65) to (9.75, -7.45)
extrude "Extrude25" cut sketch "Sketch25" along normal blind 0.3
work_plane "WorkPlane1" AlongDistance -5.8 ExtraOffset 0
sketch "Sketch1" plane through (0, 0, -5.8) normal (0, 0, 1) x axis (1, 0, 0)
  line L1 (8.4, -6.9) -> (-21.6, -6.9)
  line L2 (8.4, 13.1) -> (8.4, -6.9)
  line L3 (-21.6, 13.1) -> (8.4, 13.1)
  line L4 (-21.6, -6.9) -> (-21.6, 13.1)
extrude "Extrude1" new body sketch "Sketch1" along normal blind 5 bodies "LiPo 30x20x5"
work_plane "WorkPlane2" AlongDistance -6.5 ExtraOffset 0
sketch "Sketch2" plane through (0, 0, -6.5) normal (0, 0, 1) x axis (1, 0, 0)
  circle C1 centre (15.5, 4) radius 5
extrude "Extrude2" new body sketch "Sketch2" along normal blind 2.7 bodies "Vibration motor 10x2.7"
work_plane "WorkPlane3" AlongDistance -1.3 ExtraOffset 0
sketch "Sketch3" plane through (0, 0, -1.3) normal (0, 0, 1) x axis (1, 0, 0)
  line L1 (21.6, -24.9) -> (0.6, -24.9)
  line L2 (21.6, -7.1) -> (21.6, -24.9)
  line L3 (0.6, -7.1) -> (21.6, -7.1)
  line L4 (0.6, -24.9) -> (0.6, -7.1)
extrude "Extrude3" new body sketch "Sketch3" along normal blind 1 bodies "XIAO ESP32-S3 (upside down)"
work_plane "WorkPlane4" AlongDistance -4.5 ExtraOffset 0
sketch "Sketch4" plane through (0, 0, -4.5) normal (0, 0, 1) x axis (1, 0, 0)
  line L1 (22, -20.45) -> (14.6, -20.45)
  line L2 (22, -11.55) -> (22, -20.45)
  line L3 (14.6, -11.55) -> (22, -11.55)
  line L4 (14.6, -20.45) -> (14.6, -11.55)
extrude "Extrude4" add sketch "Sketch4" along normal blind 3.2
work_plane "WorkPlane5" AlongDistance -3.8 ExtraOffset 0
sketch "Sketch5" plane through (0, 0, -3.8) normal (0, 0, 1) x axis (1, 0, 0)
  line L1 (14.6, -23.9) -> (1.6, -23.9)
  line L2 (14.6, -8.1) -> (14.6, -23.9)
  line L3 (1.6, -8.1) -> (14.6, -8.1)
  line L4 (1.6, -23.9) -> (1.6, -8.1)
extrude "Extrude5" add sketch "Sketch5" along normal blind 2.5
work_plane "WorkPlane6" AlongDistance -6.5 ExtraOffset 0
